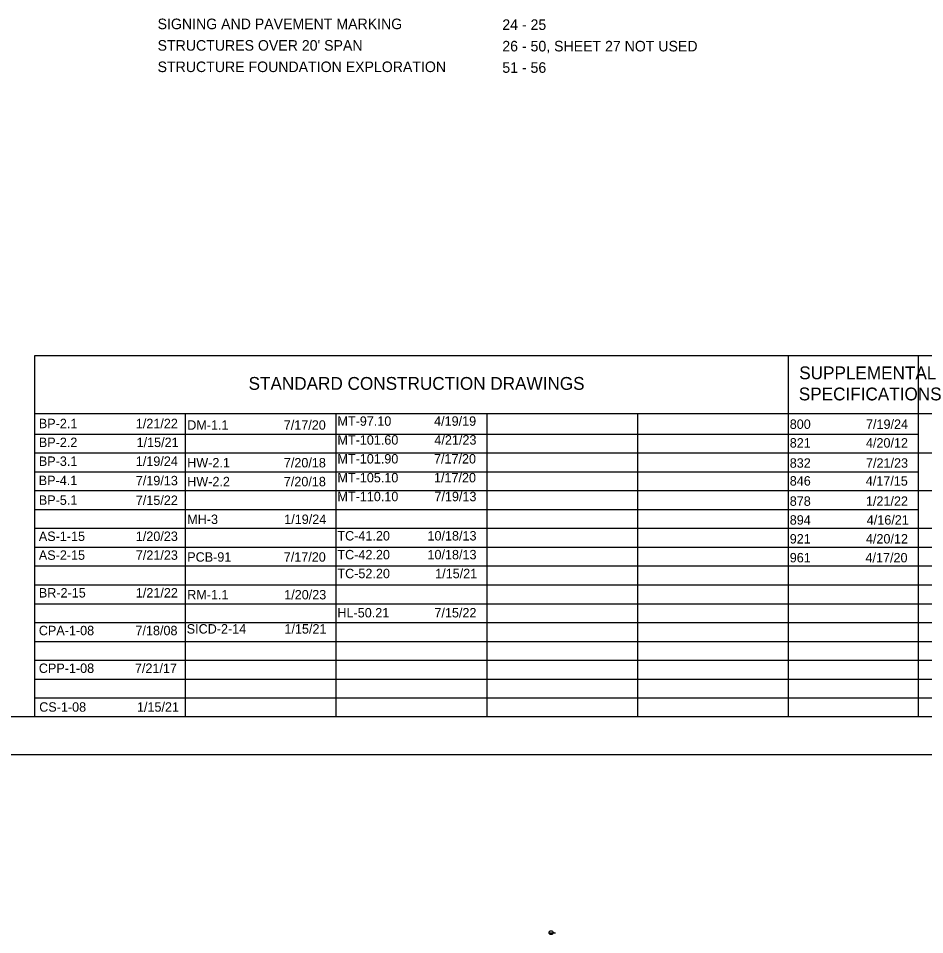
# Model space of a CAD drawing. Extents: x -4 to 116, y -17 to 29.
# Drawn here: x 58.41 to 70.44, y -16.99 to -4.84 of the extents above; entities that cross this region are included whole.
import ezdxf

# ---------------------------------------------------------------- set-up
doc = ezdxf.new("R2010")
doc.units = 0
for name, color, linetype in [('SH_Border', 7, 'Continuous'), ('SH_Cut_Line', 7, 'Continuous'), ('SH_Data', 7, 'Continuous'), ('SH_Text', 7, 'Continuous')]:
    doc.layers.add(name, color=color, linetype=linetype)

msp = doc.modelspace()

# ---------------------------------------------------------------- linework, layer by layer
at = {"layer": 'SH_Border'}
msp.add_lwpolyline([(49.983, 6.895), (81.983, 6.895), (81.983, -14.105), (49.983, -14.105)], close=True, dxfattribs=at)
at = {"layer": 'SH_Cut_Line'}
msp.add_lwpolyline([(48.483, -14.605), (82.483, -14.605), (82.483, 7.395), (48.483, 7.395)], close=True, dxfattribs=at)
at = {"layer": 'SH_Data'}
for p, q in [((58.633, -9.314), (72.083, -9.314)), ((58.633, -14.105), (58.633, -9.314)), ((68.633, -14.105), (68.633, -9.314)), ((70.358, -14.105), (70.358, -9.314)), ((58.633, -10.084), (72.083, -10.084)), ((60.633, -14.105), (60.633, -10.084)), ((62.633, -14.105), (62.633, -10.084)), ((64.633, -14.105), (64.633, -10.084)), ((66.633, -14.105), (66.633, -10.084)), ((58.633, -10.355), (70.358, -10.355)), ((58.633, -10.605), (72.083, -10.605)), ((58.633, -10.855), (70.358, -10.855)), ((58.633, -11.105), (72.083, -11.105)), ((58.633, -11.355), (70.358, -11.355)), ((58.633, -11.605), (72.083, -11.605)), ((58.633, -11.855), (72.083, -11.855)), ((58.633, -12.105), (72.083, -12.105)), ((58.633, -12.355), (72.083, -12.355)), ((58.633, -12.605), (72.083, -12.605)), ((58.633, -12.855), (72.083, -12.855)), ((58.633, -13.105), (72.083, -13.105)), ((58.633, -13.355), (72.083, -13.355)), ((58.633, -13.605), (72.083, -13.605)), ((58.633, -13.855), (72.083, -13.855))]:
    msp.add_line(p, q, dxfattribs=at)
at = {"layer": 'SH_Text'}
for p, q in [((65.457, -16.967), (65.509, -16.967)), ((65.483, -16.967), (65.543, -16.967))]:
    msp.add_line(p, q, dxfattribs=at)
msp.add_circle((65.483, -16.967), 0.026, dxfattribs=at)

# ---------------------------------------------------------------- texts
for s, height, p in [('SIGNING AND PAVEMENT MARKING', 0.14, (60.262, -4.987)), ('24 - 25', 0.14, (64.836, -4.997)), ("STRUCTURES OVER 20' SPAN ", 0.14, (60.262, -5.272)), ('26 - 50, SHEET 27 NOT USED', 0.14, (64.836, -5.282)), ('STRUCTURE FOUNDATION EXPLORATION', 0.14, (60.262, -5.556)), ('51 - 56', 0.14, (64.836, -5.566)), ('SUPPLEMENTAL', 0.17, (68.776, -9.629)), ('STANDARD CONSTRUCTION DRAWINGS', 0.17, (61.469, -9.769)), ('SPECIFICATIONS', 0.17, (68.77, -9.909)), ('BP-2.1', 0.125, (58.686, -10.278)), ('1/21/22', 0.125, (59.973, -10.278)), ('DM-1.1', 0.125, (60.655, -10.298)), ('7/17/20', 0.125, (61.936, -10.298)), ('MT-97.10', 0.125, (62.648, -10.246)), ('4/19/19', 0.125, (63.931, -10.246)), ('800', 0.125, (68.65, -10.287)), ('7/19/24', 0.125, (69.662, -10.287)), ('BP-2.2', 0.125, (58.686, -10.528)), ('1/15/21', 0.125, (59.983, -10.528)), ('MT-101.60', 0.125, (62.648, -10.496)), ('4/21/23', 0.125, (63.935, -10.496)), ('821', 0.125, (68.65, -10.535)), ('4/20/12', 0.125, (69.661, -10.535)), ('BP-3.1', 0.125, (58.686, -10.778)), ('1/19/24', 0.125, (59.973, -10.778)), ('HW-2.1', 0.125, (60.655, -10.798)), ('7/20/18', 0.125, (61.937, -10.798)), ('MT-101.90', 0.125, (62.648, -10.746)), ('7/17/20', 0.125, (63.929, -10.746)), ('832', 0.125, (68.65, -10.802)), ('7/21/23', 0.125, (69.662, -10.802)), ('BP-4.1', 0.125, (58.685, -11.033)), ('7/19/13', 0.125, (59.973, -11.035)), ('HW-2.2', 0.125, (60.655, -11.048)), ('7/20/18', 0.125, (61.937, -11.048)), ('MT-105.10', 0.125, (62.648, -10.996)), ('1/17/20', 0.125, (63.929, -10.996)), ('846', 0.125, (68.65, -11.039)), ('4/17/15', 0.125, (69.659, -11.039)), ('BP-5.1', 0.125, (58.686, -11.294)), ('7/15/22', 0.125, (59.973, -11.296)), ('MT-110.10', 0.125, (62.648, -11.246)), ('7/19/13', 0.125, (63.935, -11.246)), ('1/21/22', 0.125, (69.661, -11.307)), ('878', 0.125, (68.65, -11.307)), ('MH-3', 0.125, (60.655, -11.548)), ('1/19/24', 0.125, (61.942, -11.548)), ('894', 0.125, (68.65, -11.557)), ('4/16/21', 0.125, (69.672, -11.557)), ('AS-1-15', 0.125, (58.686, -11.773)), ('1/20/23', 0.125, (59.973, -11.773)), ('TC-41.20', 0.125, (62.648, -11.767)), ('10/18/13', 0.125, (63.843, -11.767)), ('921', 0.125, (68.65, -11.807)), ('4/20/12', 0.125, (69.661, -11.807)), ('AS-2-15', 0.125, (58.686, -12.023)), ('7/21/23', 0.125, (59.973, -12.023)), ('TC-42.20', 0.125, (62.648, -12.017)), ('10/18/13', 0.125, (63.843, -12.017)), ('PCB-91', 0.125, (60.655, -12.048)), ('7/17/20', 0.125, (61.936, -12.048)), ('961', 0.125, (68.65, -12.057)), ('4/17/20', 0.125, (69.655, -12.057)), ('TC-52.20', 0.125, (62.648, -12.267)), ('1/15/21', 0.125, (63.945, -12.267)), ('1/21/22', 0.125, (59.973, -12.523)), ('BR-2-15', 0.125, (58.686, -12.523)), ('RM-1.1', 0.125, (60.655, -12.548)), ('1/20/23', 0.125, (61.942, -12.548)), ('HL-50.21', 0.125, (62.648, -12.787)), ('7/15/22', 0.125, (63.935, -12.787)), ('SICD-2-14', 0.125, (60.648, -13.001)), ('1/15/21', 0.125, (61.945, -13.001)), ('CPA-1-08', 0.125, (58.686, -13.023)), ('7/18/08', 0.125, (59.968, -13.023)), ('CPP-1-08', 0.125, (58.686, -13.523)), ('7/21/17', 0.125, (59.961, -13.523)), ('CS-1-08', 0.125, (58.691, -14.037)), ('1/15/21', 0.125, (59.988, -14.037)), ('1', 0.00328, (65.482, -16.961)), ('1', 0.00328, (65.482, -16.977)), ('Drawing', 0.00328, (65.516, -16.961)), ('CUSTOM 1:1', 0.00328, (65.516, -16.977))]:
    msp.add_text(s, height=height, dxfattribs=at).set_placement(p)

doc.saveas('drawing.dxf')
